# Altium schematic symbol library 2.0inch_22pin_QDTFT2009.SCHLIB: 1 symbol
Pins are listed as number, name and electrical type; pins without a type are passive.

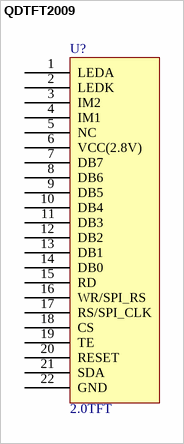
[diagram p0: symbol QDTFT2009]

## QDTFT2009
designator U?, comment 2.0TFT
2.0 TFT IPS
footprint 2.0-QY20045B0-00 (2.0 TFT IPS)
pins: 1 LEDA, 2 LEDK, 3 IM2, 4 IM1, 5 NC, 6 VCC(2.8V), 7 DB7, 8 DB6, 9 DB5, 10 DB4, 11 DB3, 12 DB2, 13 DB1, 14 DB0, 15 RD, 16 WR/SPI_RS, 17 RS/SPI_CLK, 18 CS, 19 TE, 20 RESET, 21 SDA, 22 GND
